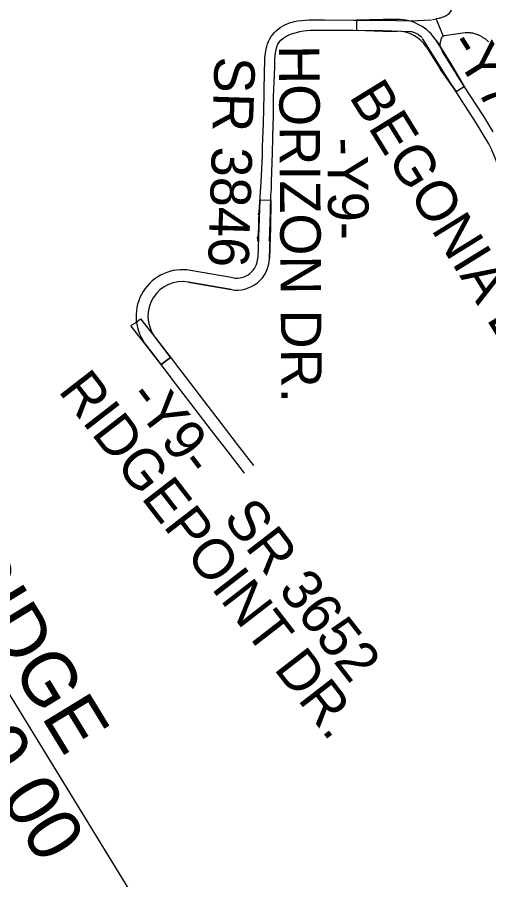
# Model space of a CAD drawing. Extents: x 1750583 to 1791140, y 783580 to 827376.
# Drawn here: x 1779520 to 1780394, y 814121 to 815720 of the extents above; entities that cross this region are included whole.
import ezdxf

# ---------------------------------------------------------------- set-up
doc = ezdxf.new("R2010")
doc.units = 0
for name, color, linetype in [('COGO Default Parcel', 7, 'Continuous'), ('Exist CMT EOP', 7, 'Continuous'), ('Prop Dimension Text', 7, 'Continuous'), ('Prop EOT', 7, 'Continuous'), ('Prop Shade Heavy', 7, 'Continuous')]:
    doc.layers.add(name, color=color, linetype=linetype)

msp = doc.modelspace()

# ---------------------------------------------------------------- linework, layer by layer
at = {"layer": 'COGO Default Parcel'}
msp.add_line((1779745.8, 814074.3), (1779070.7, 815175.4), dxfattribs=at)
at = {"layer": 'Exist CMT EOP'}
for p, q in [((1780289.8, 815716), (1780297, 815717.2)), ((1780296.9, 815717), (1780309.7, 815685.3)), ((1780301.7, 815718.1), (1780297, 815717.2)), ((1780270.4, 815683.2), (1780270.8, 815682.7)), ((1780311.8, 815686.1), (1780309.2, 815684.8)), ((1780350.7, 815691.3), (1780311.8, 815686.1)), ((1779966.6, 815355.4), (1779968.4, 815356.2)), ((1779964.7, 815312.1), (1779967, 815309.6))]:
    msp.add_line(p, q, dxfattribs=at)
for points in [[(1780089.6, 815715.2), (1780143.5, 815715), (1780196.9, 815714.8), (1780249, 815713.5), (1780288.5, 815715.7)], [(1780089.5, 815696.4), (1780143.4, 815696.5), (1780197.4, 815696), (1780249.1, 815694)], [(1780394.3, 815485.6), (1780369.8, 815526.1), (1780359.9, 815541.7), (1780348.4, 815559.7), (1780317.8, 815607.2), (1780294.9, 815643.7), (1780271.6, 815680.7)], [(1780309.7, 815653.7), (1780333.2, 815616), (1780334.4, 815614.1)], [(1780402.6, 815507.8), (1780385.7, 815535.4), (1780358.4, 815577), (1780334.9, 815613.5)], [(1779966.6, 815305), (1779968.2, 815329.9), (1779968.3, 815344.1), (1779968.5, 815359.2), (1779972.7, 815414.6), (1779974.8, 815463.6), (1779975.1, 815469.1), (1779975, 815480.5), (1779977, 815523.3), (1779977.9, 815576.9)], [(1779988, 815304.9), (1779989.8, 815358.1), (1779990.6, 815391), (1779991.7, 815401.2), (1779991.6, 815415.1), (1779993.3, 815469.2), (1779994.8, 815522.8), (1779995.4, 815533.3), (1779995.6, 815542.4), (1779995.5, 815576.4)], [(1779731.2, 815148.7), (1779739.3, 815153.7), (1779748.9, 815161.2), (1779778.3, 815123.4), (1779807.9, 815085), (1779813.2, 815078.5), (1779825.3, 815062.6), (1779837.6, 815046), (1779867.6, 815007.1), (1779898.4, 814967.1), (1779928.3, 814928.3), (1779958.5, 814889.2)], [(1779941.8, 814875.4), (1779911.2, 814914.8), (1779880.7, 814954), (1779850.2, 814994), (1779820.1, 815033.1), (1779809.1, 815047.1), (1779797, 815063.3), (1779790.8, 815071.5), (1779760.7, 815110.3), (1779731.8, 815147.9)]]:
    msp.add_lwpolyline(points, dxfattribs=at)
msp.add_ellipse((1780225.5, 815393.3), major_axis=(175.1, -79.7), ratio=0.999841, start_param=0.461351, end_param=0.927272, dxfattribs=at)
for points in [[(1780038.8, 816235.9), (1780067.4, 816193.3), (1780094.4, 816152.1), (1780121.1, 816111.6), (1780148.1, 816070.1), (1780175.4, 816028.8), (1780200.8, 815983), (1780224.3, 815939.3), (1780249.1, 815897.3), (1780274.7, 815853.1), (1780298.7, 815810), (1780322.9, 815765.9), (1780327.4, 815755.6), (1780327, 815740.9), (1780321.8, 815728.6), (1780307.1, 815719.7), (1780301.7, 815718.1)], [(1779977.9, 815576.9), (1779979, 815631.9), (1779982.8, 815666.1), (1779991.2, 815684.3), (1780020.4, 815708.1), (1780033.9, 815712.1), (1780089.6, 815715.2)], [(1779995.5, 815576.4), (1779997.7, 815631.3), (1780006.4, 815674.5), (1780037.7, 815692.3), (1780089.5, 815696.4)], [(1780249.1, 815694), (1780256.7, 815692.2), (1780261.5, 815689.8), (1780265.6, 815687), (1780270.5, 815683.1), (1780270.4, 815683.2)], [(1780309.2, 815684.8), (1780307, 815681.8), (1780305.6, 815679.1), (1780304.9, 815676.1), (1780304.2, 815672.9), (1780303.7, 815669.3), (1780303.7, 815668.4), (1780304.5, 815666.6), (1780306.5, 815661.4), (1780309.7, 815653.7)], [(1780394.6, 815674.5), (1780389.8, 815678.6), (1780385.1, 815681.7), (1780380.6, 815684.5), (1780376, 815686.9), (1780370.9, 815688.8), (1780366.4, 815690.2), (1780360.2, 815691.2), (1780350.7, 815691.3)]]:
    msp.add_spline(points, degree=3, dxfattribs=at)
at = {"layer": 'Prop EOT'}
for p, q in [((1780198.9, 815716.3), (1780148.9, 815714.9)), ((1780148.9, 815714.9), (1780148.9, 815696.4)), ((1780198.9, 815716.3), (1780224.6, 815716.4)), ((1780215.9, 815716.3), (1780224.6, 815716.4)), ((1780148.9, 815696.5), (1780198.9, 815694.3)), ((1780198.9, 815694.3), (1780224.7, 815694.4)), ((1780215.9, 815694.3), (1780224.7, 815694.4)), ((1780278.8, 815664.7), (1780305, 815623.6)), ((1780297.3, 815676.6), (1780323.6, 815635.4)), ((1780323.6, 815635.4), (1780348.7, 815592.1)), ((1780333.7, 815582.6), (1780305, 815623.6)), ((1780333.7, 815582.6), (1780348.7, 815592.1)), ((1780341.1, 815587.3), (1780345.4, 815590)), ((1779967.9, 815331.3), (1779970.1, 815381.2)), ((1779990.4, 815380.6), (1779970.1, 815381.2)), ((1779990.4, 815380.6), (1779989.9, 815330.6)), ((1779967.9, 815331.3), (1779966.1, 815274.3)), ((1779989.9, 815330.6), (1779988.1, 815273.6)), ((1779920.4, 815237.1), (1779841.4, 815250.9)), ((1779916.7, 815215.4), (1779837.6, 815229.2)), ((1779804.4, 815089.5), (1779787.2, 815076.3))]:
    msp.add_line(p, q, dxfattribs=at)
for centre, radius, start, end in [((1780224.8, 815630.4), 86, 32.4829, 90.1351), ((1780224.8, 815630.4), 64, 32.4829, 90.1351), ((1779927.1, 815275.5), 61, 260.1094, 358.1618), ((1779927.1, 815275.5), 39, 260.1094, 358.1618), ((1779826.6, 815166.2), 86, 80.1094, 215.4204), ((1779826.6, 815166.2), 64, 80.1094, 215.4204)]:
    msp.add_arc(centre, radius, start, end, dxfattribs=at)
for points in [[(1779774.4, 815129.1), (1779774.8, 815128.6), (1779775.1, 815128.1), (1779775.4, 815127.7), (1779775.8, 815127.2), (1779776.2, 815126.7), (1779776.6, 815126.1), (1779777, 815125.6), (1779777.4, 815125.1), (1779777.8, 815124.5), (1779778.2, 815124), (1779778.6, 815123.4), (1779779.1, 815122.9), (1779779.5, 815122.4), (1779779.9, 815121.8), (1779780.3, 815121.3), (1779780.7, 815120.8), (1779781.1, 815120.2), (1779781.5, 815119.7), (1779781.9, 815119.1), (1779782.3, 815118.6), (1779782.7, 815118.1), (1779783.1, 815117.5), (1779783.6, 815117), (1779784, 815116.4), (1779784.4, 815115.9), (1779784.8, 815115.4), (1779785.2, 815114.8), (1779785.6, 815114.3), (1779786, 815113.8), (1779786.4, 815113.2), (1779786.8, 815112.7), (1779787.2, 815112.1), (1779787.6, 815111.6), (1779788, 815111.1), (1779788.5, 815110.5), (1779788.9, 815110), (1779789.3, 815109.5), (1779789.7, 815108.9), (1779790.1, 815108.4), (1779790.5, 815107.8), (1779790.9, 815107.3), (1779791.3, 815106.8), (1779791.7, 815106.2), (1779792.1, 815105.7), (1779792.5, 815105.2), (1779793, 815104.6), (1779793.4, 815104.1), (1779793.8, 815103.5), (1779794.2, 815103), (1779794.6, 815102.5), (1779795, 815101.9), (1779795.4, 815101.4), (1779795.8, 815100.8), (1779796.2, 815100.3), (1779796.6, 815099.8), (1779797, 815099.2), (1779797.5, 815098.7), (1779797.9, 815098.2), (1779798.3, 815097.6), (1779798.7, 815097.1), (1779799.1, 815096.5), (1779799.5, 815096), (1779799.9, 815095.5), (1779800.3, 815094.9), (1779800.7, 815094.4), (1779801.1, 815093.9), (1779801.5, 815093.3), (1779801.9, 815092.8), (1779802.4, 815092.2), (1779802.8, 815091.7), (1779803.2, 815091.2), (1779803.6, 815090.6), (1779804.4, 815089.5)], [(1779756.5, 815116.3), (1779757, 815115.7), (1779757.4, 815115.1), (1779757.9, 815114.4), (1779758.4, 815113.8), (1779758.8, 815113.3), (1779759.2, 815112.7), (1779759.6, 815112.2), (1779760, 815111.7), (1779760.4, 815111.1), (1779760.8, 815110.6), (1779761.2, 815110.1), (1779761.7, 815109.5), (1779762.1, 815109), (1779762.5, 815108.5), (1779762.9, 815107.9), (1779763.3, 815107.4), (1779763.7, 815106.8), (1779764.1, 815106.3), (1779764.5, 815105.8), (1779765, 815105.2), (1779765.4, 815104.7), (1779765.8, 815104.2), (1779766.2, 815103.6), (1779766.6, 815103.1), (1779767, 815102.6), (1779767.4, 815102), (1779767.8, 815101.5), (1779768.2, 815101), (1779768.7, 815100.4), (1779769.1, 815099.9), (1779769.5, 815099.3), (1779769.9, 815098.8), (1779770.3, 815098.3), (1779770.7, 815097.7), (1779771.1, 815097.2), (1779771.5, 815096.7), (1779772, 815096.1), (1779772.4, 815095.6), (1779772.8, 815095.1), (1779773.2, 815094.5), (1779773.6, 815094), (1779774, 815093.5), (1779774.4, 815092.9), (1779774.8, 815092.4), (1779775.2, 815091.8), (1779775.7, 815091.3), (1779776.1, 815090.8), (1779776.5, 815090.2), (1779776.9, 815089.7), (1779777.3, 815089.2), (1779777.7, 815088.6), (1779778.1, 815088.1), (1779778.5, 815087.6), (1779779, 815087), (1779779.4, 815086.5), (1779779.8, 815086), (1779780.2, 815085.4), (1779780.6, 815084.9), (1779781, 815084.3), (1779781.4, 815083.8), (1779781.8, 815083.3), (1779782.3, 815082.7), (1779782.7, 815082.2), (1779783.1, 815081.7), (1779783.5, 815081.1), (1779783.9, 815080.6), (1779784.3, 815080.1), (1779784.7, 815079.5), (1779785.1, 815079), (1779785.5, 815078.5), (1779786, 815077.9), (1779786.4, 815077.4), (1779787.2, 815076.3)]]:
    msp.add_spline(points, degree=3, dxfattribs=at)
at = {"layer": 'Prop Shade Heavy'}
for p, q in [((1780198.9, 815716.3), (1780148.9, 815714.9)), ((1780148.9, 815714.9), (1780148.9, 815696.5)), ((1780148.9, 815696.5), (1780198.9, 815694.3)), ((1780198.9, 815694.3), (1780215.9, 815694.3)), ((1780215.9, 815694.3), (1780224.7, 815694.4)), ((1780278.8, 815664.7), (1780305, 815623.6)), ((1780323.6, 815635.4), (1780297.3, 815676.6)), ((1780348.7, 815592.1), (1780323.6, 815635.4)), ((1780305, 815623.6), (1780333.7, 815582.6)), ((1780333.7, 815582.6), (1780341.1, 815587.3)), ((1780341.1, 815587.3), (1780345.4, 815590)), ((1780345.4, 815590), (1780348.7, 815592.1)), ((1779970.1, 815381.2), (1779967.9, 815331.3)), ((1779990.4, 815380.6), (1779970.1, 815381.2)), ((1779989.9, 815330.6), (1779990.4, 815380.6)), ((1779967.9, 815331.3), (1779966.1, 815274.3)), ((1779988.1, 815273.6), (1779989.9, 815330.6)), ((1779920.4, 815237.1), (1779841.4, 815250.9)), ((1779837.6, 815229.2), (1779916.7, 815215.4)), ((1779787.2, 815076.3), (1779804.4, 815089.5))]:
    msp.add_line(p, q, dxfattribs=at)
msp.add_lwpolyline([(1780224.6, 815716.4), (1780215.9, 815716.3), (1780198.9, 815716.3)], dxfattribs=at)
for centre, radius, start, end in [((1780224.8, 815630.4), 86, 32.4829, 90.1351), ((1780224.8, 815630.4), 64, 32.4829, 90.1351), ((1779927.1, 815275.5), 61, 260.1094, 358.1618), ((1779927.1, 815275.5), 39, 260.1094, 358.1618), ((1779826.6, 815166.2), 86, 80.1094, 215.4204), ((1779826.6, 815166.2), 64, 80.1094, 215.4204)]:
    msp.add_arc(centre, radius, start, end, dxfattribs=at)
for points in [[(1779784.4, 815115.9), (1779784.4, 815115.9), (1779784.4, 815115.9), (1779784.4, 815115.9), (1779784.2, 815116.1), (1779784.1, 815116.3), (1779784, 815116.4), (1779783.8, 815116.6), (1779783.7, 815116.8), (1779783.6, 815117), (1779783.4, 815117.2), (1779783.3, 815117.3), (1779783.1, 815117.5), (1779783, 815117.7), (1779782.9, 815117.9), (1779782.7, 815118.1), (1779782.6, 815118.2), (1779782.5, 815118.4), (1779782.3, 815118.6), (1779782.2, 815118.8), (1779782.1, 815119), (1779781.9, 815119.1), (1779781.8, 815119.3), (1779781.6, 815119.5), (1779781.5, 815119.7), (1779781.4, 815119.9), (1779781.2, 815120), (1779781.1, 815120.2), (1779781, 815120.4), (1779780.8, 815120.6), (1779780.7, 815120.8), (1779780.6, 815120.9), (1779780.4, 815121.1), (1779780.3, 815121.3), (1779780.1, 815121.5), (1779780, 815121.6), (1779779.9, 815121.8), (1779779.7, 815122), (1779779.6, 815122.2), (1779779.5, 815122.4), (1779779.3, 815122.5), (1779779.2, 815122.7), (1779779.1, 815122.9), (1779778.9, 815123.1), (1779778.8, 815123.3), (1779778.6, 815123.4), (1779778.5, 815123.6), (1779778.4, 815123.8), (1779778.2, 815124), (1779778.1, 815124.2), (1779778, 815124.3), (1779777.8, 815124.5), (1779777.7, 815124.7), (1779777.6, 815124.9), (1779777.4, 815125.1), (1779777.3, 815125.2), (1779777.1, 815125.4), (1779777, 815125.6), (1779776.9, 815125.8), (1779776.7, 815126), (1779776.6, 815126.1), (1779776.5, 815126.3), (1779776.3, 815126.5), (1779776.2, 815126.7), (1779776.1, 815126.8), (1779775.9, 815127), (1779775.8, 815127.2), (1779775.7, 815127.4), (1779775.6, 815127.5), (1779775.4, 815127.7), (1779775.3, 815127.8), (1779775.2, 815128), (1779775.1, 815128.1), (1779775, 815128.3), (1779774.9, 815128.4), (1779774.8, 815128.6), (1779774.7, 815128.7), (1779774.5, 815128.9), (1779774.4, 815129.1)], [(1779756.5, 815116.3), (1779756.7, 815116.1), (1779756.8, 815115.9), (1779757, 815115.7), (1779757.1, 815115.5), (1779757.3, 815115.3), (1779757.4, 815115.1), (1779757.6, 815114.8), (1779757.7, 815114.6), (1779757.9, 815114.4), (1779758, 815114.2), (1779758.2, 815114), (1779758.4, 815113.8), (1779758.5, 815113.6), (1779758.6, 815113.5), (1779758.8, 815113.3), (1779758.9, 815113.1), (1779759, 815112.9), (1779759.2, 815112.7), (1779759.3, 815112.6), (1779759.5, 815112.4), (1779759.6, 815112.2), (1779759.7, 815112), (1779759.9, 815111.8), (1779760, 815111.7), (1779760.1, 815111.5), (1779760.3, 815111.3), (1779760.4, 815111.1), (1779760.6, 815111), (1779760.7, 815110.8), (1779760.8, 815110.6), (1779761, 815110.4), (1779761.1, 815110.2), (1779761.2, 815110.1), (1779761.4, 815109.9), (1779761.5, 815109.7), (1779761.7, 815109.5), (1779761.8, 815109.3), (1779761.9, 815109.2), (1779762.1, 815109), (1779762.2, 815108.8), (1779762.3, 815108.6), (1779762.5, 815108.5), (1779762.6, 815108.3), (1779762.8, 815108.1), (1779762.9, 815107.9), (1779763, 815107.7), (1779763.2, 815107.6), (1779763.3, 815107.4), (1779763.4, 815107.2), (1779763.6, 815107), (1779763.7, 815106.8), (1779763.9, 815106.7), (1779764, 815106.5), (1779764.1, 815106.3), (1779764.3, 815106.1), (1779764.4, 815106), (1779764.5, 815105.8), (1779764.7, 815105.6), (1779764.8, 815105.4), (1779765, 815105.2), (1779765.1, 815105.1), (1779765.2, 815104.9), (1779765.4, 815104.7), (1779765.5, 815104.5), (1779765.6, 815104.3), (1779765.8, 815104.2), (1779765.9, 815104), (1779766, 815103.8), (1779766.2, 815103.6), (1779766.3, 815103.5), (1779766.5, 815103.3), (1779766.6, 815103.1), (1779766.6, 815103), (1779766.7, 815103), (1779766.7, 815103)], [(1779794.4, 815102.7), (1779794.3, 815102.8), (1779794.3, 815102.9), (1779794.2, 815103), (1779794, 815103.2), (1779793.9, 815103.4), (1779793.8, 815103.5), (1779793.6, 815103.7), (1779793.5, 815103.9), (1779793.4, 815104.1), (1779793.2, 815104.3), (1779793.1, 815104.4), (1779793, 815104.6), (1779792.8, 815104.8), (1779792.7, 815105), (1779792.5, 815105.2), (1779792.4, 815105.3), (1779792.3, 815105.5), (1779792.1, 815105.7), (1779792, 815105.9), (1779791.9, 815106), (1779791.7, 815106.2), (1779791.6, 815106.4), (1779791.5, 815106.6), (1779791.3, 815106.8), (1779791.2, 815106.9), (1779791, 815107.1), (1779790.9, 815107.3), (1779790.8, 815107.5), (1779790.6, 815107.7), (1779790.5, 815107.8), (1779790.4, 815108), (1779790.2, 815108.2), (1779790.1, 815108.4), (1779790, 815108.6), (1779789.8, 815108.7), (1779789.7, 815108.9), (1779789.5, 815109.1), (1779789.4, 815109.3), (1779789.3, 815109.5), (1779789.1, 815109.6), (1779789, 815109.8), (1779788.9, 815110), (1779788.7, 815110.2), (1779788.6, 815110.4), (1779788.5, 815110.5), (1779788.3, 815110.7), (1779788.2, 815110.9), (1779788, 815111.1), (1779787.9, 815111.2), (1779787.8, 815111.4), (1779787.6, 815111.6), (1779787.5, 815111.8), (1779787.4, 815112), (1779787.2, 815112.1), (1779787.1, 815112.3), (1779787, 815112.5), (1779786.8, 815112.7), (1779786.7, 815112.9), (1779786.6, 815113), (1779786.4, 815113.2), (1779786.3, 815113.4), (1779786.1, 815113.6), (1779786, 815113.8), (1779785.9, 815113.9), (1779785.7, 815114.1), (1779785.6, 815114.3), (1779785.5, 815114.5), (1779785.3, 815114.7), (1779785.2, 815114.8), (1779785.1, 815115), (1779784.9, 815115.2), (1779784.8, 815115.4), (1779784.7, 815115.5), (1779784.5, 815115.7), (1779784.4, 815115.9)], [(1779766.7, 815103), (1779766.8, 815102.8), (1779766.9, 815102.7), (1779767, 815102.6), (1779767.1, 815102.4), (1779767.3, 815102.2), (1779767.4, 815102), (1779767.6, 815101.8), (1779767.7, 815101.7), (1779767.8, 815101.5), (1779768, 815101.3), (1779768.1, 815101.1), (1779768.2, 815101), (1779768.4, 815100.8), (1779768.5, 815100.6), (1779768.7, 815100.4), (1779768.8, 815100.2), (1779768.9, 815100.1), (1779769.1, 815099.9), (1779769.2, 815099.7), (1779769.3, 815099.5), (1779769.5, 815099.3), (1779769.6, 815099.2), (1779769.8, 815099), (1779769.9, 815098.8), (1779770, 815098.6), (1779770.2, 815098.5), (1779770.3, 815098.3), (1779770.4, 815098.1), (1779770.6, 815097.9), (1779770.7, 815097.7), (1779770.9, 815097.6), (1779771, 815097.4), (1779771.1, 815097.2), (1779771.3, 815097), (1779771.4, 815096.8), (1779771.5, 815096.7), (1779771.7, 815096.5), (1779771.8, 815096.3), (1779772, 815096.1), (1779772.1, 815096), (1779772.2, 815095.8), (1779772.4, 815095.6), (1779772.5, 815095.4), (1779772.6, 815095.2), (1779772.8, 815095.1), (1779772.9, 815094.9), (1779773.1, 815094.7), (1779773.2, 815094.5), (1779773.3, 815094.3), (1779773.5, 815094.2), (1779773.6, 815094), (1779773.7, 815093.8), (1779773.9, 815093.6), (1779774, 815093.5), (1779774.1, 815093.3), (1779774.3, 815093.1), (1779774.4, 815092.9), (1779774.6, 815092.7), (1779774.7, 815092.6), (1779774.8, 815092.4), (1779775, 815092.2), (1779775.1, 815092), (1779775.2, 815091.8), (1779775.4, 815091.7), (1779775.5, 815091.5), (1779775.7, 815091.3), (1779775.8, 815091.1), (1779775.9, 815091), (1779776.1, 815090.8), (1779776.2, 815090.6), (1779776.3, 815090.4), (1779776.5, 815090.2), (1779776.6, 815090.1), (1779776.8, 815089.9), (1779776.9, 815089.7), (1779776.9, 815089.7), (1779776.9, 815089.7), (1779776.9, 815089.6)], [(1779776.9, 815089.6), (1779777.1, 815089.5), (1779777.2, 815089.3), (1779777.3, 815089.2), (1779777.4, 815089), (1779777.6, 815088.8), (1779777.7, 815088.6), (1779777.9, 815088.5), (1779778, 815088.3), (1779778.1, 815088.1), (1779778.3, 815087.9), (1779778.4, 815087.7), (1779778.5, 815087.6), (1779778.7, 815087.4), (1779778.8, 815087.2), (1779779, 815087), (1779779.1, 815086.8), (1779779.2, 815086.7), (1779779.4, 815086.5), (1779779.5, 815086.3), (1779779.6, 815086.1), (1779779.8, 815086), (1779779.9, 815085.8), (1779780.1, 815085.6), (1779780.2, 815085.4), (1779780.3, 815085.2), (1779780.5, 815085.1), (1779780.6, 815084.9), (1779780.7, 815084.7), (1779780.9, 815084.5), (1779781, 815084.3), (1779781.2, 815084.2), (1779781.3, 815084), (1779781.4, 815083.8), (1779781.6, 815083.6), (1779781.7, 815083.5), (1779781.8, 815083.3), (1779782, 815083.1), (1779782.1, 815082.9), (1779782.3, 815082.7), (1779782.4, 815082.6), (1779782.5, 815082.4), (1779782.7, 815082.2), (1779782.8, 815082), (1779782.9, 815081.9), (1779783.1, 815081.7), (1779783.2, 815081.5), (1779783.3, 815081.3), (1779783.5, 815081.1), (1779783.6, 815081), (1779783.8, 815080.8), (1779783.9, 815080.6), (1779784, 815080.4), (1779784.2, 815080.2), (1779784.3, 815080.1), (1779784.4, 815079.9), (1779784.6, 815079.7), (1779784.7, 815079.5), (1779784.9, 815079.4), (1779785, 815079.2), (1779785.1, 815079), (1779785.3, 815078.8), (1779785.4, 815078.6), (1779785.5, 815078.5), (1779785.7, 815078.3), (1779785.8, 815078.1), (1779786, 815077.9), (1779786.1, 815077.7), (1779786.2, 815077.6), (1779786.4, 815077.4), (1779786.6, 815077), (1779786.9, 815076.7), (1779787.2, 815076.3)], [(1779804.4, 815089.5), (1779804.1, 815089.9), (1779803.9, 815090.3), (1779803.6, 815090.6), (1779803.4, 815090.8), (1779803.3, 815091), (1779803.2, 815091.2), (1779803, 815091.3), (1779802.9, 815091.5), (1779802.8, 815091.7), (1779802.6, 815091.9), (1779802.5, 815092.1), (1779802.4, 815092.2), (1779802.2, 815092.4), (1779802.1, 815092.6), (1779801.9, 815092.8), (1779801.8, 815093), (1779801.7, 815093.1), (1779801.5, 815093.3), (1779801.4, 815093.5), (1779801.3, 815093.7), (1779801.1, 815093.9), (1779801, 815094), (1779800.9, 815094.2), (1779800.7, 815094.4), (1779800.6, 815094.6), (1779800.4, 815094.7), (1779800.3, 815094.9), (1779800.2, 815095.1), (1779800, 815095.3), (1779799.9, 815095.5), (1779799.8, 815095.6), (1779799.6, 815095.8), (1779799.5, 815096), (1779799.4, 815096.2), (1779799.2, 815096.4), (1779799.1, 815096.5), (1779799, 815096.7), (1779798.8, 815096.9), (1779798.7, 815097.1), (1779798.5, 815097.3), (1779798.4, 815097.4), (1779798.3, 815097.6), (1779798.1, 815097.8), (1779798, 815098), (1779797.9, 815098.2), (1779797.7, 815098.3), (1779797.6, 815098.5), (1779797.5, 815098.7), (1779797.3, 815098.9), (1779797.2, 815099.1), (1779797, 815099.2), (1779796.9, 815099.4), (1779796.8, 815099.6), (1779796.6, 815099.8), (1779796.5, 815099.9), (1779796.4, 815100.1), (1779796.2, 815100.3), (1779796.1, 815100.5), (1779796, 815100.7), (1779795.8, 815100.8), (1779795.7, 815101), (1779795.5, 815101.2), (1779795.4, 815101.4), (1779795.3, 815101.6), (1779795.1, 815101.7), (1779795, 815101.9), (1779794.9, 815102.1), (1779794.7, 815102.3), (1779794.6, 815102.5), (1779794.5, 815102.5), (1779794.5, 815102.6), (1779794.4, 815102.7)]]:
    msp.add_open_spline(points, degree=3, dxfattribs=at)

# ---------------------------------------------------------------- texts
at = {"layer": 'Prop Dimension Text'}
for s, height, rotation, p in [('-Y7-', 75, 302.0944, (1780317.2, 815670.1)), ('HORIZON DR.', 75, 270.3975, (1780005.4, 815668.4)), ('SR 3846', 75, 268.1893, (1779886.5, 815648.1)), ('BEGONIA DR.', 75, 301.7096, (1780134.2, 815573.4)), ('-Y9-', 75, 270.7839, (1780094.7, 815496.6)), ('BEGIN BRIDGE', 100, 301.4017, (1779107, 815172.3)), ('-Y- STA. 37+99.00', 100, 301.4017, (1778986, 815095.6)), ('RIDGEPOINT DR.', 75, 307.8036, (1779594.9, 815027.6)), ('-Y9-', 75, 307.421, (1779723.2, 815015.3)), ('SR 3652', 75, 307.8036, (1779900.1, 814790.8))]:
    msp.add_text(s, height=height, rotation=rotation, dxfattribs=at).set_placement(p)

doc.saveas('drawing.dxf')
